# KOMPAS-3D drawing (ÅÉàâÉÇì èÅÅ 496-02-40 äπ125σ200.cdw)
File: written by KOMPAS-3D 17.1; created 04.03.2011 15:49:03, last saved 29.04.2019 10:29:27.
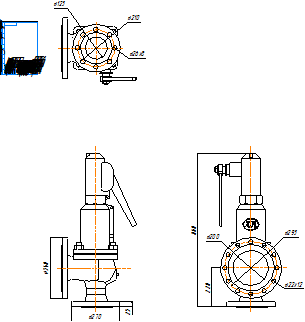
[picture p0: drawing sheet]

Sheet 1: A4, portrait

Title block, sheet 1: name: ПРЕГРАН КПП 496-02-40 / Ду125х200; material: Внимание! Данный продукт является объектом авторского права ООО «Торговый Дом АДЛ». / Запрещается изменение, копирование, распространение / (в том числе путем копирования на другие сайты и ресурсы в Интернете) / или любое иное использование информации и объектов без предварительного / согласия правообладателя (ООО «Торговый Дом АДЛ»).; scale: 1:1; sheets: 1; organisation: ООО "Торговый дом АДЛ"; sheet format: A4; stored path: C:\Users\tra\Desktop\2д чертежи\Предохранительные клапаны ПРЕГРАН\ПРЕГРАН 496\ПРЕГРАН КПП 496-02-40\KOMPAS 2D\ПРЕГРАН КПП 496-02-40 Ду125х200.cdw

Views: Спереди 1, Проекционный вид 2, Проекционный вид 3
Dimensions and other numbers on the sheet: 270; 340; 220; 860; 295; 22; 200; 210; 125; 25; 26; 1:1; 1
